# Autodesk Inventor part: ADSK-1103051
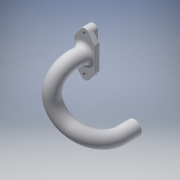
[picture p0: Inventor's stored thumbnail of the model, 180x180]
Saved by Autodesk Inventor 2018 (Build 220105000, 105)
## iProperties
Shininess: 41.0
Length Units: 11272
Angle Units: 11279
Time Units: 11290
Mass Units: 11286
Length Display Precision: 4
Angle Display Precision: 2
Compacted: True
Created: 2000-08
Part Number: ADSK-1103051
Document SubType Name: Modeling
Mass: 3.87512 g
Surface Area: 71.1546 cm^2
Volume: 3.87512 cm^3
Density: 1 g/cm^3
Material: Generic
Appearance: Default
Density: 0.0
Volumn: 0.0
Area: 0.0
PropertySet Name: Model Information
Control State: 0
Master: False
Checked Out: False
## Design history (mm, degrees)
node "Extrusion1" dims "d0" = 3.175, "d1" = 0
  sketch "Sketch3"
    geometry: L1 (-24.5, -3.018)-(-24.5, 22.982) reference; L2 (-23, 0.482)-(-23, 18.482) reference; L3 (-22, 19.482)-(-20, 19.482) reference; L4 (-17.5, 22.982)-(-17.5, -3.018) reference; L5 (-19, 18.482)-(-19, 0.482) reference; L6 (-20, -0.518)-(-22, -0.518) reference; A1 r 3.5 centre (-21, 22.982) between (-17.5, 22.982) and (-24.5, 22.982) reference; A2 r 1 centre (-22, 18.482) between (-22, 19.482) and (-23, 18.482) reference; A3 r 1 centre (-20, 18.482) between (-19, 18.482) and (-20, 19.482) reference; A4 r 3.5 centre (-21, -3.018) between (-24.5, -3.018) and (-17.5, -3.018) reference; A5 r 1 centre (-22, 0.482) between (-23, 0.482) and (-22, -0.518) reference; A6 r 1 centre (-20, 0.482) between (-20, -0.518) and (-19, 0.482) reference
    constraints: 12 end point, 12 point on circle, 6 centre point, 4 vertical, 2 horizontal, 24 other
node "Extrusion2" dims "d4" = 3.175, "d5" = 0
  sketch "Sketch4"
    geometry: L1 (-19, 18.482)-(-19, 0.482) reference; L2 (-24.5, -3.018)-(-24.5, 22.982) reference; L3 (-17.5, 22.982)-(-17.5, -3.018) reference; L4 (-23.785, -5.139)-(-28.62, 1.211); L5 (-28.62, 1.211)-(-28.62, 18.752); L6 (-28.62, 18.752)-(-23.785, 25.102); L7 (-18.215, -5.139)-(-13.38, 1.211); L8 (-13.38, 1.211)-(-13.38, 18.752); L9 (-13.38, 18.752)-(-18.215, 25.102); A1 r 3.5 centre (-21, 22.982) between (-17.5, 22.982) and (-24.5, 22.982) reference; A2 r 3.5 centre (-21, -3.018) between (-24.5, -3.018) and (-17.5, -3.018) reference
    constraints: 12 end point, 4 parallel, 4 point on circle, 4 tangent, 2 equal length
    dimensions: "d2" = 15.24 distance between parallel lines of L8 L5; "d3" = 6.35 vertical distance of L4.start L4.end
node "Loft1" dims "d7" = 3.3, "d8" = 90 deg, "d9" = 3.3, "d10" = 90 deg
  sketch "Sketch5"
    geometry: L1 (22, 19.482)-(20, 19.482) reference; L2 (19, 18.482)-(19, 0.482) reference; L3 (20, -0.518)-(22, -0.518) reference; L4 (23, 0.482)-(23, 18.482) reference; A1 r 1 centre (20, 18.482) between (20, 19.482) and (19, 18.482) reference; A2 r 1 centre (20, 0.482) between (19, 0.482) and (20, -0.518) reference; A3 r 1 centre (22, 0.482) between (22, -0.518) and (23, 0.482) reference; A4 r 1 centre (22, 18.482) between (23, 18.482) and (22, 19.482) reference
  sketch "Sketch6"
    geometry: L1 (-28.62, 1.211)-(-28.62, 18.752) reference; L2 (-21, -3.018)-(-21, 22.982); C1 r 4.445 at (-21, 9.982); A1 r 3.5 centre (-21, 22.982) between (-18.215, 25.102) and (-23.785, 25.102) reference; A2 r 3.5 centre (-21, -3.018) between (-23.785, -5.139) and (-18.215, -5.139) reference
    constraints: 2 end point, 1 centre point, 1 midpoint, 1 parallel
    dimensions: "d6" = 8.89 diameter of C1
node "Revolution1" dims "d14" = 15 deg
  sketch "Sketch7"
    geometry: L1 (-28.62, 1.211)-(-28.62, 18.752) reference; L2 (-13.38, 18.752)-(-13.38, 1.211) reference; C1 r 5.274 at (-21, 9.982); A1 r 3.5 centre (-21, -3.018) between (-23.785, -5.139) and (-18.215, -5.139) reference; 9 further points
    constraints: 2 horizontal alignment, 2 vertical alignment, 1 centre point, 1 midpoint, 6 other
    dimensions: "d12" = 10.54862 diameter of C1
node "Revolution2" dims "d15" = 94 deg
  sketch "Sketch8"
    geometry: L1 (6.987, -17.795)-(-7.412, -17.795); C1 r 5.274 at (0, 0) reference; 8 further points
    constraints: 2 end point, 1 horizontal, 1 horizontal alignment, 1 vertical alignment, 6 other
node "Revolution3" dims "d16" = 60 deg
  sketch "Sketch9"
    geometry: L1 (19.108, -8.183)-(22.735, 4.959); C1 r 5.274 at (0, 0) reference; 8 further points
    constraints: 2 end point, 8 other
node "Revolution4" dims "d17" = 75 deg
  sketch "Sketch10"
    geometry: L1 (20.068, 21.365)-(23.424, -2.949); L2 (8.121, 19.463)-(55.018, 25.936) reference; C1 r 5.274 at (0, 0) reference; 8 further points
    constraints: 2 end point, 1 perpendicular, 8 other
    dimensions: "d21" = 22.8011 distance from line of C1.centre L1
node "Extrusion3" dims "d18" = 9.525, "d19" = 0
  sketch "Sketch11"
    geometry: C1 r 5.274 at (0, 0) reference; 8 further points
    constraints: 8 other
fillet "Fillet2" dims "d22" = 2.54
fillet "Fillet4" dims "d24" = 0.3175
fillet "Fillet5" dims "d25" = 3.175
workaxis "Work Axis1"
hole "Hole1" diameter "d28" = 2.45872; stored, may be unused: countersink angle "d32" = 82 deg, drill point angle "d34" = 118 deg; dims "d26" = 25.4, "d27" = 25.4, "d29" = 12.7, "d30" = 9.525, "d31" = 6.35, "d33" = 19.05
hole "Hole2" diameter "d37" = 2.45872; stored, may be unused: countersink angle "d41" = 82 deg, drill point angle "d43" = 118 deg; dims "d35" = 25.4, "d36" = 25.4, "d38" = 12.7, "d39" = 9.525, "d40" = 6.35, "d42" = 19.05
body "Solid1"
